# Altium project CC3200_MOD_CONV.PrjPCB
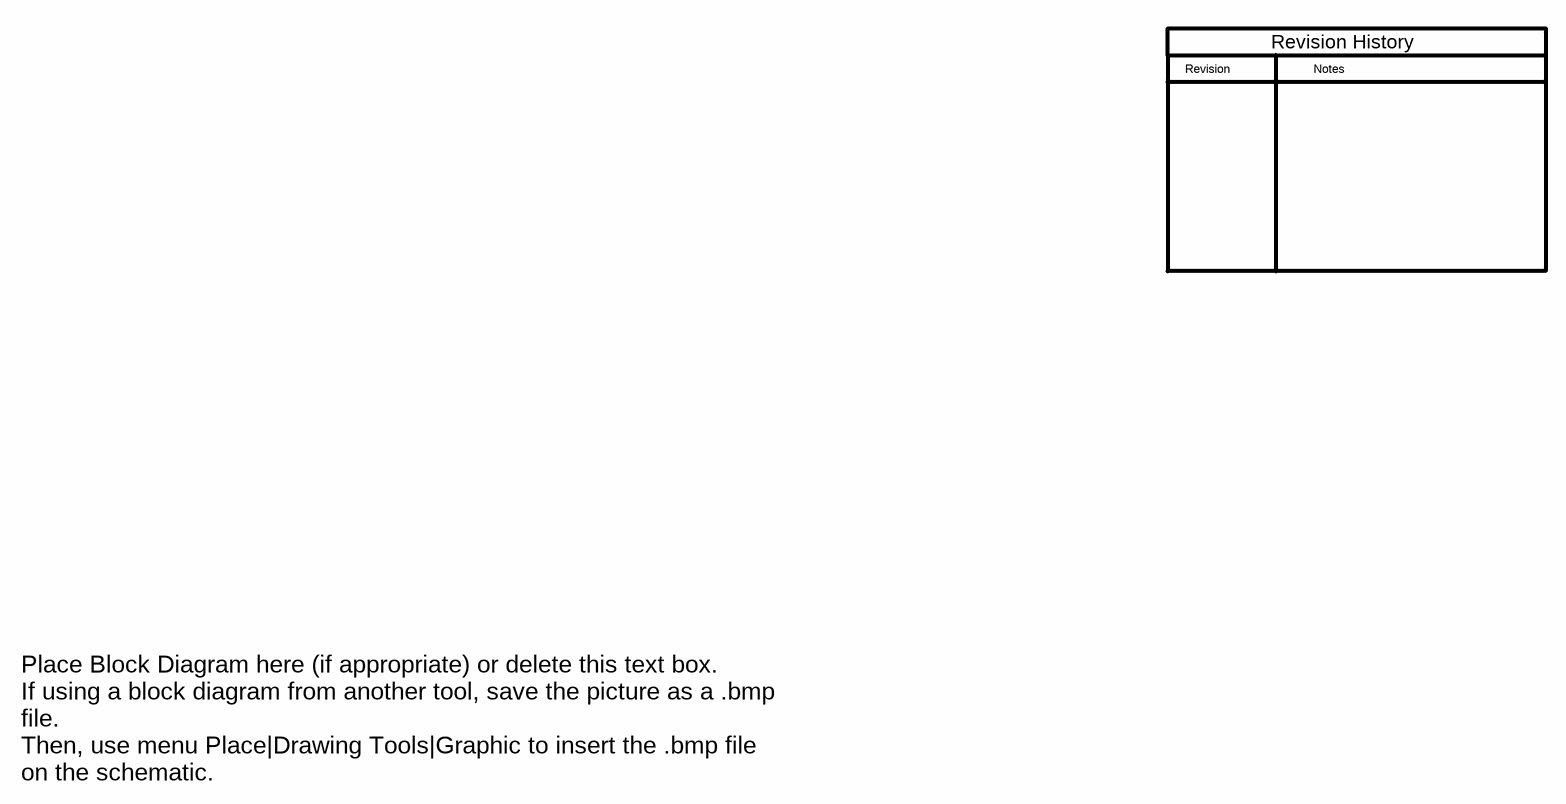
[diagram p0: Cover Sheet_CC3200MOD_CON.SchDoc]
TechSupport: http://www.ti.com/support; SCH_Rev: 1.0; PRJ_Title: Change in menu Project|Project Options|Parameters; PRJ_Number: TIDC-WIFI-METER-READING; PRJ_Engineer: Mars Leung; PRJ_Customer: Public Release; PCB_Rev: 1.0; PCB_Layout: Mars Leung; CopyrightYear: 2015
3 sheets, 82 parts. Net scope: flat (ports and power ports of the same name join across sheets).
Board file: CC3200MOD_CONV.PcbDoc
Sheets:
  Cover Sheet_CC3200MOD_CON.SchDoc
  CC3200MOD_CONV.SchDoc
  Hardware_CC3200MOD_CONV.SchDoc

## Sheet Cover Sheet_CC3200MOD_CON.SchDoc
size 431 x 279 mm; Date: Not shown in title block; ApprovedBy: Not shown in title block; CheckedBy: Not shown in title block; Author: Not shown in title block; CompanyName: Not shown in title block; Engineer: Not shown in title block; Organization: Not shown in title block; Address1: Not shown in title block; Address2: Not shown in title block; Address3: Not shown in title block; Address4: Not shown in title block; DocumentNumber: 1; Revision: Use project parameter SCH_Rev; SheetNumber: 1; SheetTotal: 1; PageSetup: Record=PageOptions|CenterHorizontal=True|CenterVertical=True|PrintScale=1.00|XCorrection=1.00|YCorrection=1.00|PrintKind=0|BorderSize=5000000|LeftOffset=0|BottomOffset=0|Orientation=2|PaperLength=1000|PaperWidth=1000|Scale=100|PaperSource=15|PrintQuality=600|MediaType=1|DitherType=10|PaperKind=Letter|PrintScaleMode=1

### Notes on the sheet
- Revision
- Notes
- Revision History
- Place Block Diagram here (if appropriate) or delete this text box.
  If using a block diagram from another tool, save the picture as a .bmp file.
  Then, use menu Place|Drawing Tools|Graphic to insert the .bmp file on the schematic.

## Sheet CC3200MOD_CONV.SchDoc: TIDC-WIFI-METER-READING
size 431 x 279 mm; Date: Not shown in title block; ApprovedBy: Not shown in title block; CheckedBy: Not shown in title block; Author: Not shown in title block; CompanyName: Not shown in title block; Engineer: Not shown in title block; Organization: Not shown in title block; Address1: Not shown in title block; Address2: Not shown in title block; Address3: Not shown in title block; Address4: Not shown in title block; DocumentNumber: 1; Revision: Use project parameter SCH_Rev; SheetNumber: 1; SheetTotal: 1; PageSetup: Record=PageOptions¦CenterHorizontal=True¦CenterVertical=True¦PrintScale=1.00¦XCorrection=1.00¦YCorrection=1.00¦PrintKind=0¦BorderSize=5000000¦LeftOffset=0¦BottomOffset=0¦Orientation=2¦PaperLength=1000¦PaperWidth=1000¦Scale=100¦PaperSource=15¦PrintQuality=600¦MediaType=1¦DitherType=10¦PaperKind=Letter¦PrintScaleMode=1
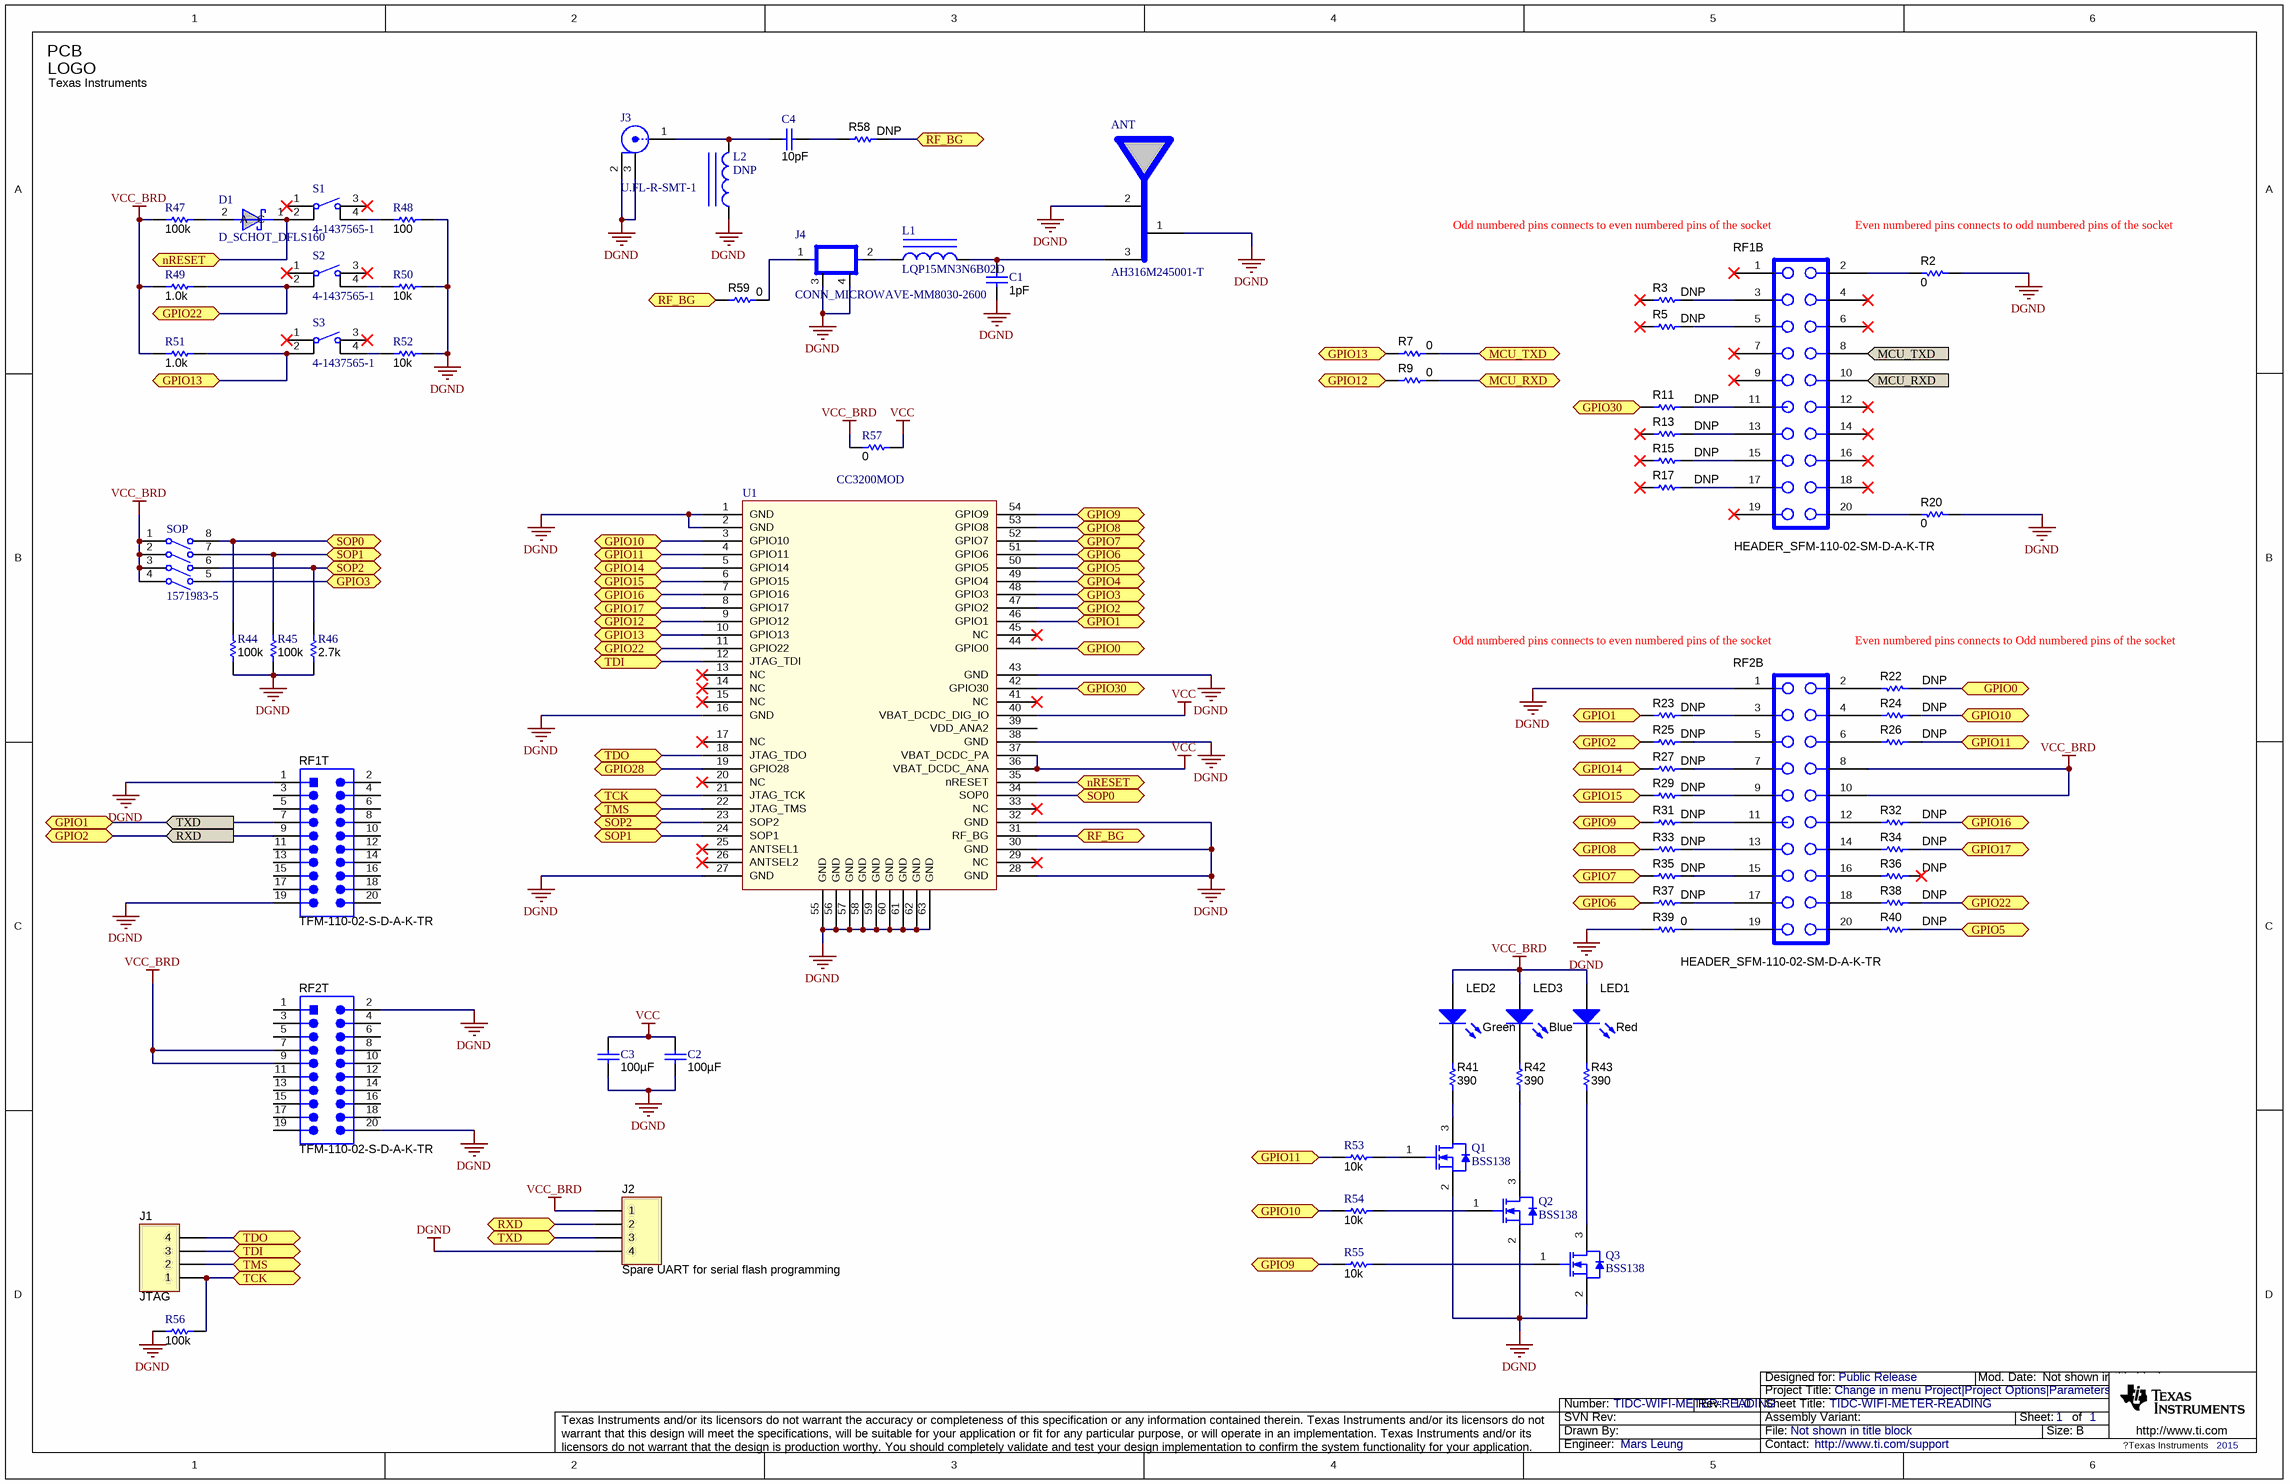
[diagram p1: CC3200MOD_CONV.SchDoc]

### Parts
ANT  AH316M245001-T  [AH316M]
C1  ValueDisplayed: 1pF  [0402]  (hidden comment: GRM1555C1H1R0BA01D)
C2  ValueDisplayed: 100µF  [1210]  (hidden comment: GRM32ER60J107ME20L)
C3  ValueDisplayed: 100µF  [1210]  (hidden comment: GRM32ER60J107ME20L)
C4  ValueDisplayed: 10pF  [0402]  (hidden comment: GRM1555C1H100JA01D)
D1  D_SCHOT_DFLS160  [POWERDI_123]
J1  JTAG  [HDR1X4]
J2  Spare UART for serial flash programming  [HDR1X4]
J3  U.FL-R-SMT-1  [CONN_UFL-R-SMT-1]
J4  CONN_MICROWAVE-MM8030-2600  [CONN_MICRO-MM8030-2600]
L1  LQP15MN3N6B02D  [LQP_0402]
L2  DNP  [LQP_0402]
LED1  Red  [0805-LED]
LED2  Green  [0805-LED]
LED3  Blue  [0805-LED]
Logo1  Texas Instruments  [TI_Stacked_SolderMask_Small]  (no BOM)
Q1  BSS138  [SOT-23]
Q2  BSS138  [SOT-23]
Q3  BSS138  [SOT-23]
R2  ValueDisplayed: 0  [0402]  (hidden comment: CRCW04020000Z0ED)
R3  ValueDisplayed: DNP  [0402]  (hidden comment: CRCW04020000Z0ED (Phantom))
R5  ValueDisplayed: DNP  [0402]  (hidden comment: CRCW04020000Z0ED (Phantom))
R7  ValueDisplayed: 0  [0402]  (hidden comment: CRCW04020000Z0ED)
R9  ValueDisplayed: 0  [0402]  (hidden comment: CRCW04020000Z0ED)
R11  ValueDisplayed: DNP  [0402]  (hidden comment: CRCW04020000Z0ED (Phantom))
R13  ValueDisplayed: DNP  [0402]  (hidden comment: CRCW04020000Z0ED (Phantom))
R15  ValueDisplayed: DNP  [0402]  (hidden comment: CRCW04020000Z0ED (Phantom))
R17  ValueDisplayed: DNP  [0402]  (hidden comment: CRCW04020000Z0ED (Phantom))
R20  ValueDisplayed: 0  [0402]  (hidden comment: CRCW04020000Z0ED)
R22  ValueDisplayed: DNP  [0402]  (hidden comment: CRCW04020000Z0ED (Phantom))
R23  ValueDisplayed: DNP  [0402]  (hidden comment: CRCW04020000Z0ED (Phantom))
R24  ValueDisplayed: DNP  [0402]  (hidden comment: CRCW04020000Z0ED (Phantom))
R25  ValueDisplayed: DNP  [0402]  (hidden comment: CRCW04020000Z0ED (Phantom))
R26  ValueDisplayed: DNP  [0402]  (hidden comment: CRCW04020000Z0ED (Phantom))
R27  ValueDisplayed: DNP  [0402]  (hidden comment: CRCW04020000Z0ED (Phantom))
R29  ValueDisplayed: DNP  [0402]  (hidden comment: CRCW04020000Z0ED (Phantom))
R31  ValueDisplayed: DNP  [0402]  (hidden comment: CRCW04020000Z0ED (Phantom))
R32  ValueDisplayed: DNP  [0402]  (hidden comment: CRCW04020000Z0ED (Phantom))
R33  ValueDisplayed: DNP  [0402]  (hidden comment: CRCW04020000Z0ED (Phantom))
R34  ValueDisplayed: DNP  [0402]  (hidden comment: CRCW04020000Z0ED (Phantom))
R35  ValueDisplayed: DNP  [0402]  (hidden comment: CRCW04020000Z0ED (Phantom))
R36  ValueDisplayed: DNP  [0402]  (hidden comment: CRCW04020000Z0ED (Phantom))
R37  ValueDisplayed: DNP  [0402]  (hidden comment: CRCW04020000Z0ED (Phantom))
R38  ValueDisplayed: DNP  [0402]  (hidden comment: CRCW04020000Z0ED (Phantom))
R39  ValueDisplayed: 0  [0402]  (hidden comment: CRCW04020000Z0ED)
R40  ValueDisplayed: DNP  [0402]  (hidden comment: CRCW04020000Z0ED (Phantom))
R41  ValueDisplayed: 390  [0402]  (hidden comment: CRCW0402390RJNED)
R42  ValueDisplayed: 390  [0402]  (hidden comment: CRCW0402390RJNED)
R43  ValueDisplayed: 390  [0402]  (hidden comment: CRCW0402390RJNED)
R44  ValueDisplayed: 100k  [0402]  (hidden comment: CRCW0402100KJNED)
R45  ValueDisplayed: 100k  [0402]  (hidden comment: CRCW0402100KJNED)
R46  ValueDisplayed: 2.7k  [0402]  (hidden comment: CRCW04022K70JNED)
R47  ValueDisplayed: 100k  [0402]  (hidden comment: CRCW0402100KJNED)
R48  ValueDisplayed: 100  [0402]  (hidden comment: CRCW0402100RJNED)
R49  ValueDisplayed: 1.0k  [0402]  (hidden comment: CRCW04021K00JNED)
R50  ValueDisplayed: 10k  [0402]  (hidden comment: CRCW040210K0JNED)
R51  ValueDisplayed: 1.0k  [0402]  (hidden comment: CRCW04021K00JNED)
R52  ValueDisplayed: 10k  [0402]  (hidden comment: CRCW040210K0JNED)
R53  ValueDisplayed: 10k  [0402]  (hidden comment: CRCW040210K0JNED)
R54  ValueDisplayed: 10k  [0402]  (hidden comment: CRCW040210K0JNED)
R55  ValueDisplayed: 10k  [0402]  (hidden comment: CRCW040210K0JNED)
R56  ValueDisplayed: 100k  [0402]  (hidden comment: CRCW0402100KJNED)
R57  ValueDisplayed: 0  [0805_HV]  (hidden comment: CRCW08050000Z0EA)
R58  ValueDisplayed: DNP  [0402]  (hidden comment: CRCW04020000Z0ED (Phantom))
R59  ValueDisplayed: 0  [0402]  (hidden comment: CRCW04020000Z0ED)
RF1B  HEADER_SFM-110-02-SM-D-A-K-TR  [HEADER_TFM-110-02-SM]
RF1T  TFM-110-02-S-D-A-K-TR  [Samtec_TFM-110-02-S-D-A-K]
RF2B  HEADER_SFM-110-02-SM-D-A-K-TR  [HEADER_TFM-110-02-SM]
RF2T  TFM-110-02-S-D-A-K-TR  [Samtec_TFM-110-02-S-D-A-K]
S1  4-1437565-1  [SW_FSM4JSMA]
S2  4-1437565-1  [SW_FSM4JSMA]
S3  4-1437565-1  [SW_FSM4JSMA]
SOP  1571983-5  [SW_1571983-5]
U1  CC3200MOD  [CC3200MOD]

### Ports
GPIO0, GPIO1, GPIO2, GPIO3, GPIO4, GPIO5, GPIO6, GPIO7, GPIO8, GPIO9, GPIO10, GPIO11, GPIO12, GPIO13, GPIO14, GPIO15, GPIO16, GPIO17, GPIO22, GPIO28, GPIO30, MCU_RXD, MCU_TXD, nRESET, RF_BG, RXD, SOP0, SOP1, SOP2, TCK, TDI, TDO, TMS, TXD

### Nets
DGND: ANT.1 ANT.2 C1.1 C2.2 C3.2 J2.4 J3.2 J3.3 J4.3 J4.4 L2.1 Q1.2(S) Q2.2(S) Q3.2(S) R2.1 R20.1 R39.1 R44.1 R45.1 R46.1 R48.2 R50.2 R52.2 R56.1 RF1T.1 RF1T.19 RF2B.1 RF2T.2 RF2T.20 U1.1(GND) U1.2(GND) U1.16(GND) U1.27(GND) U1.28(GND) U1.30(GND) U1.32(GND) U1.38(GND) U1.43(GND) U1.55(GND) U1.56(GND) U1.57(GND) U1.58(GND) U1.59(GND) U1.60(GND) U1.61(GND) U1.62(GND) U1.63(GND)
VCC: C2.1 C3.1 R57.2 U1.36(VBAT_DCDC_ANA) U1.37(VBAT_DCDC_PA) U1.40(VBAT_DCDC_DIG_IO)
VCC_BRD: J2.1 LED1.1(A) LED2.1(A) LED3.1(A) R47.1 R49.1 R51.1 R57.1 RF2B.8 RF2B.10 RF2T.7 RF2T.9 SOP.1(A1) SOP.2(A2) SOP.3(A3) SOP.4(A4)
GPIO0: R22.1 U1.44(GPIO0) ; port GPIO0
GPIO1: J2.3 R23.1 RF1T.7 U1.46(GPIO1) ; port TXD, port GPIO1
GPIO2: J2.2 R25.1 RF1T.9 U1.47(GPIO2) ; port RXD, port GPIO2
GPIO3: SOP.5(B4) U1.48(GPIO3) ; port GPIO3
GPIO4: U1.49(GPIO4) ; port GPIO4
GPIO5: R40.2 U1.50(GPIO5) ; port GPIO5
GPIO6: R37.1 U1.51(GPIO6) ; port GPIO6
GPIO7: R35.1 U1.52(GPIO7) ; port GPIO7
GPIO8: R33.1 U1.53(GPIO8) ; port GPIO8
GPIO9: R31.1 R55.1 U1.54(GPIO9) ; port GPIO9
GPIO10: R24.2 R54.1 U1.3(GPIO10) ; port GPIO10
GPIO11: R26.2 R53.1 U1.4(GPIO11) ; port GPIO11
GPIO12: R9.1 U1.9(GPIO12) ; port GPIO12
GPIO13: R7.1 R51.2 S3.2 U1.10(GPIO13) ; port GPIO13
GPIO14: R27.1 U1.5(GPIO14) ; port GPIO14
GPIO15: R29.1 U1.6(GPIO15) ; port GPIO15
GPIO16: R32.2 U1.7(GPIO16) ; port GPIO16
GPIO17: R34.2 U1.8(GPIO17) ; port GPIO17
GPIO22: R38.2 R49.2 S2.2 U1.11(GPIO22) ; port GPIO22
GPIO28: U1.19(GPIO28) ; port GPIO28
GPIO30: R11.1 U1.42(GPIO30) ; port GPIO30
MCU_RXD: R9.2 RF1B.10 ; port MCU_RXD
MCU_TXD: R7.2 RF1B.8 ; port MCU_TXD
nRESET: D1.1(C) S1.2 U1.35(nRESET) ; port nRESET
RF_BG: R58.2 R59.1 U1.31(RF_BG) ; port RF_BG
SOP0: R44.2 SOP.8(B1) U1.34(SOP0) ; port SOP0
SOP1: R45.2 SOP.7(B2) U1.24(SOP1) ; port SOP1
SOP2: R46.2 SOP.6(B3) U1.23(SOP2) ; port SOP2
TCK: J1.1 R56.2 U1.21(JTAG_TCK) ; port TCK
TDI: J1.3 U1.12(JTAG_TDI) ; port TDI
TDO: J1.4 U1.18(JTAG_TDO) ; port TDO
TMS: J1.2 U1.22(JTAG_TMS) ; port TMS
NetANT_3: ANT.3 C1.2 L1.2
NetC4_1: C4.1 R58.1
NetC4_2: C4.2 J3.1 L2.2
NetD1_2: D1.2(A) R47.2
NetJ4_1: J4.1 R59.2
NetJ4_2: J4.2 L1.1
NetLED1_2: LED1.2(K) R43.2
NetLED2_2: LED2.2(K) R41.2
NetLED3_2: LED3.2(K) R42.2
NetQ1_1: Q1.1(G) R53.2
NetQ1_3: Q1.3(D) R41.1
NetQ2_1: Q2.1(G) R54.2
NetQ2_3: Q2.3(D) R42.1
NetQ3_1: Q3.1(G) R55.2
NetQ3_3: Q3.3(D) R43.1
NetR2_2: R2.2 RF1B.2
NetR3_2: R3.2 RF1B.3
NetR5_2: R5.2 RF1B.5
NetR11_2: R11.2 RF1B.11
NetR13_2: R13.2 RF1B.13
NetR15_2: R15.2 RF1B.15
NetR17_2: R17.2 RF1B.17
NetR20_2: R20.2 RF1B.20
NetR22_2: R22.2 RF2B.2
NetR23_2: R23.2 RF2B.3
NetR24_1: R24.1 RF2B.4
NetR25_2: R25.2 RF2B.5
NetR26_1: R26.1 RF2B.6
NetR27_2: R27.2 RF2B.7
NetR29_2: R29.2 RF2B.9
NetR31_2: R31.2 RF2B.11
NetR32_1: R32.1 RF2B.12
NetR33_2: R33.2 RF2B.13
NetR34_1: R34.1 RF2B.14
NetR35_2: R35.2 RF2B.15
NetR36_1: R36.1 RF2B.16
NetR37_2: R37.2 RF2B.17
NetR38_1: R38.1 RF2B.18
NetR39_2: R39.2 RF2B.19
NetR40_1: R40.1 RF2B.20
NetR48_1: R48.1 S1.4
NetR50_1: R50.1 S2.4
NetR52_1: R52.1 S3.4

Not connected (* = marked no-connect by the designer): R3 1*; R5 1*; R13 1*; R15 1*; R17 1*; R36 2*; RF1B 1* 4* 6* 7* 9* 12* 14* 16* 18* 19*; RF1T 2 3 4 5 6 8 10 11 12 13 14 15 16 17 18 20; RF2T 1 3 4 5 6 8 10 11 12 13 14 15 16 17 18 19; S1 1* 3*; S2 1* 3*; S3 1* 3*; U1 13(NC)* 14(NC)* 15(NC)* 17(NC)* 20(NC)* 25(ANTSEL1)* 26(ANTSEL2)* 29(NC)* 33(NC)* 39(VDD_ANA2) 41(NC)* 45(NC)*

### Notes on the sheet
- (near RF1B) Odd numbered pins connects to even numbered pins of the socket
- Even numbered pins connects to odd numbered pins of the socket
- (near RF2B) Odd numbered pins connects to even numbered pins of the socket
- Even numbered pins connects to Odd numbered pins of the socket

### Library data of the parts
ANT = AH316M245001-T: Manufacturer: Taiyo Yuden; Value: 2.45-GHz Ant
C1 = GRM1555C1H1R0BA01D: CAP, CERM, 1 pF, 50 V, +/- 10%, C0G/NP0, 0402; Manufacturer: MuRata; Polarized: N; CompType: Capacitor; Value: 1pF; U/M: EA; Cap_F: 0.000000000001; Tolerance_%: 10; Value1: Unknown; VDC_V: 50; Value2: 50V; TaMin_C: -55; TaMax_C: 125
C2 C3 = GRM32ER60J107ME20L: CAP, CERM, 100 µF, 6.3 V, +/- 20%, X5R, 1210; Manufacturer: MuRata; Polarized: N; CompType: Capacitor; Value: 100uF; U/M: EA; Cap_F: 0.0001; Tolerance_%: 20; ESR_ohm: 0.002; Value1: 0.002 ohm; VDC_V: 6.3; Value2: 6.3V; TaMin_C: -55; TaMax_C: 85
C4 = GRM1555C1H100JA01D: CAP, CERM, 10 pF, 50 V, +/- 5%, C0G/NP0, 0402; Manufacturer: MuRata; Polarized: N; CompType: Capacitor; Value: 10pF; U/M: EA; Cap_F: 0.00000000001; Tolerance_%: 5; Value1: Unknown; VDC_V: 50; Value2: 50V; TaMin_C: -55; TaMax_C: 125
D1 = D_SCHOT_DFLS160: Diode, Schottky, 1A, 60V; Manufacturer: Diodes; Area: 53200
J1 J2 = Header 4: Header, 4-Pin
J3 = U.FL-R-SMT-1: Connector, Ultra-Mini Coaxial, SMD; Manufacturer: Hirose Electric Co. Ltd.; SymbolCreator: a0412235; U/M: EA
J4 = CONN_MICROWAVE-MM8030-2600: Connector, Micrwave, 50 Ohm Coax; Manufacturer: murata; Area: 9 mm
L1 = LQP15MN10NG02D: Inductor, Film,  3.6 nH, 0.1 A, 1.3 ohm, SMD; Manufacturer: MuRata; Value: 3.6nH; Ind_H: 3.6E-9; Imax_A: 0.1; Irms: 0.1A @ C rise; DCR_ohm: 0.5; Value1: 0.5 ohm; Value2: 0.1A
L2 = LQP15MN10NG02D: Inductor, Film,  3.6 nH, 0.1 A, 1.3 ohm, SMD; PartNumber: LQP15MN3N6B02D; Manufacturer: MuRata; Ind_H: 3.6E-9; ValueDisplayed: 3.6nH; Imax_A: 0.1; Irms: 0.1A @ C rise; DCR_ohm: 0.5; Value1: 0.5 ohm; Value2: 0.1A
LED1-LED3 = LED-0805: Manufacturer: Used in BOM report; SymbolVersion: use current date i.e. 2008-05-20; SymbolCreator: Use LDAP id; CompType: Used in some BOM reports.  Useful for finding later.; U/M: EA, IN, or GM
Logo1 = TI_Logo: Texas Instrument Corporate Signature; SymbolCreator: codlsc
Q1-Q3 = BSS138: MOSFET, N-CH, 50 V, 0.22 A, SOT-23; Manufacturer: Fairchild Semiconductor; Alternate Manufacturer: None; U/M: EA; ChType: N; Value: 50V; VdsMax_V: 50; Value1: 6 ohm; Rdson45_ohm: 6; Value2: 1.7 nC; QgTyp_nC: 1.7; Vgs_V: 20; IdsMax_A: 0.22
R2 R7 R9 R20 R39 R59 = CRCW04020000Z0ED: RES, 0, 5%, 0.063 W, 0402; Manufacturer: Vishay-Dale; CompType: Resistor; Value: 0; Value_Code: 0000; Tolerance_%: 5; Power_W: 0.063; Value2: 0.063W; VDC_V: 50; TempCo: 200 ppm/C; EIA_Code: E24; U/M: EA
R3 R5 R11 R13 R15 R17 R22-R27 R29 R31-R38 R40 R58 = CRCW04020000Z0ED: RES, DNP, 5%, 0.063 W, 0402; Manufacturer: Vishay-Dale; CompType: Resistor; Value_Code: 0000; Tolerance_%: 5; Power_W: 0.063; Value2: 0.063W; VDC_V: 50; TempCo: 200 ppm/C; EIA_Code: E24; U/M: EA
R41-R43 = CRCW0402390RJNED: RES, 390, 5%, 0.063 W, 0402; Manufacturer: Vishay-Dale; CompType: Resistor; Value: 390; Value_Code: 390R; Tolerance_%: 5; Power_W: 0.063; Value2: 0.063W; VDC_V: 50; TempCo: 200 ppm/C; EIA_Code: E24; U/M: EA
R44 R45 R47 R56 = CRCW0402100KJNED: RES, 100 k, 5%, 0.063 W, 0402; Manufacturer: Vishay-Dale; CompType: Resistor; Value: 100k; Res_ohm: 100000; Tolerance_%: 5; Power_W: 0.063; Value2: 0.063W; VDC_V: 50; TempCo: 200 ppm/C; EIA_Code: E24; U/M: EA
R46 = CRCW04022K70JNED: RES, 2.7 k, 5%, 0.063 W, 0402; Manufacturer: Vishay-Dale; CompType: Resistor; Value: 2.7k; Res_ohm: 2700; Value_Code: 2k70; Tolerance_%: 5; Power_W: 0.063; Value2: 0.063W; VDC_V: 50; TempCo: 200 ppm/C; EIA_Code: E24; U/M: EA
R48 = CRCW0402100RJNED: RES, 100, 5%, 0.063 W, 0402; Manufacturer: Vishay-Dale; CompType: Resistor; Value: 100; Value_Code: 100R; Tolerance_%: 5; Power_W: 0.063; Value2: 0.063W; VDC_V: 50; TempCo: 200 ppm/C; EIA_Code: E24; U/M: EA
R49 R51 = CRCW04021K00JNED: RES, 1.0 k, 5%, 0.063 W, 0402; Manufacturer: Vishay-Dale; CompType: Resistor; Value: 1.0k; Res_ohm: 1000; Value_Code: 1k00; Tolerance_%: 5; Power_W: 0.063; Value2: 0.063W; VDC_V: 50; TempCo: 200 ppm/C; EIA_Code: E24; U/M: EA
R50 R52-R55 = CRCW040210K0JNED: RES, 10 k, 5%, 0.063 W, 0402; Manufacturer: Vishay-Dale; CompType: Resistor; Value: 10k; Res_ohm: 10000; Value_Code: 10k0; Tolerance_%: 5; Power_W: 0.063; Value2: 0.063W; VDC_V: 50; TempCo: 200 ppm/C; EIA_Code: E24; U/M: EA
R57 = CRCW08050000Z0EA: RES, 0, 5%, 0.125 W, 0805; Manufacturer: Vishay-Dale; CompType: Resistor; Value: 0; Value_Code: 0000; Tolerance_%: 5; Power_W: 0.125; Value2: 0.125W; VDC_V: 150; TempCo: 200 ppm/C; EIA_Code: E24; U/M: EA
RF1B RF2B = HEADER_TFM-110-02-SM-D-A-K-TR: Header, SMT 10X2 pin, Shrouded; Manufacturer: Samtec; area: 119800
RF1T RF2T = TFM-110-02-S-D-A-K-TR: CONN SHRD HDR HDR 20 POS 1.27MM SLDR ST SMD; Manufacturer: Samtec; SymbolCreator: a0412235; CompType: Header; U/M: EA
S1-S3 = 4-1437565-1: Switch, Tactile, SPST-NO, 0.05A, 12V, SMT; Manufacturer: TE Connectivity; SymbolCreator: a0412235; VDC_V: 12; SwitchFunction: Off-Mom; PositionCount: 1; CurrentRating_mA: 50
SOP = 1571983-5: Switch, SPST, 4 Pos, Top Actuated, SMD; Manufacturer: TE Connectivity; SymbolCreator: a0412235; VDC_V: 24; PositionCount: 4; CurrentRating_mA: 25

## Sheet Hardware_CC3200MOD_CONV.SchDoc: TIDC-WIFI-METER-READING
size 431 x 279 mm; Date: Not shown in title block; ApprovedBy: Not shown in title block; CheckedBy: Not shown in title block; Author: Not shown in title block; CompanyName: Not shown in title block; Engineer: Not shown in title block; Organization: Not shown in title block; Address1: Not shown in title block; Address2: Not shown in title block; Address3: Not shown in title block; Address4: Not shown in title block; DocumentNumber: 1; Revision: Use project parameter SCH_Rev; SheetNumber: 1; SheetTotal: 1; PageSetup: Record=PageOptions¦CenterHorizontal=True¦CenterVertical=True¦PrintScale=1.00¦XCorrection=1.00¦YCorrection=1.00¦PrintKind=0¦BorderSize=5000000¦LeftOffset=0¦BottomOffset=0¦Orientation=2¦PaperLength=1000¦PaperWidth=1000¦Scale=100¦PaperSource=15¦PrintQuality=600¦MediaType=1¦DitherType=10¦PaperKind=Letter¦PrintScaleMode=1
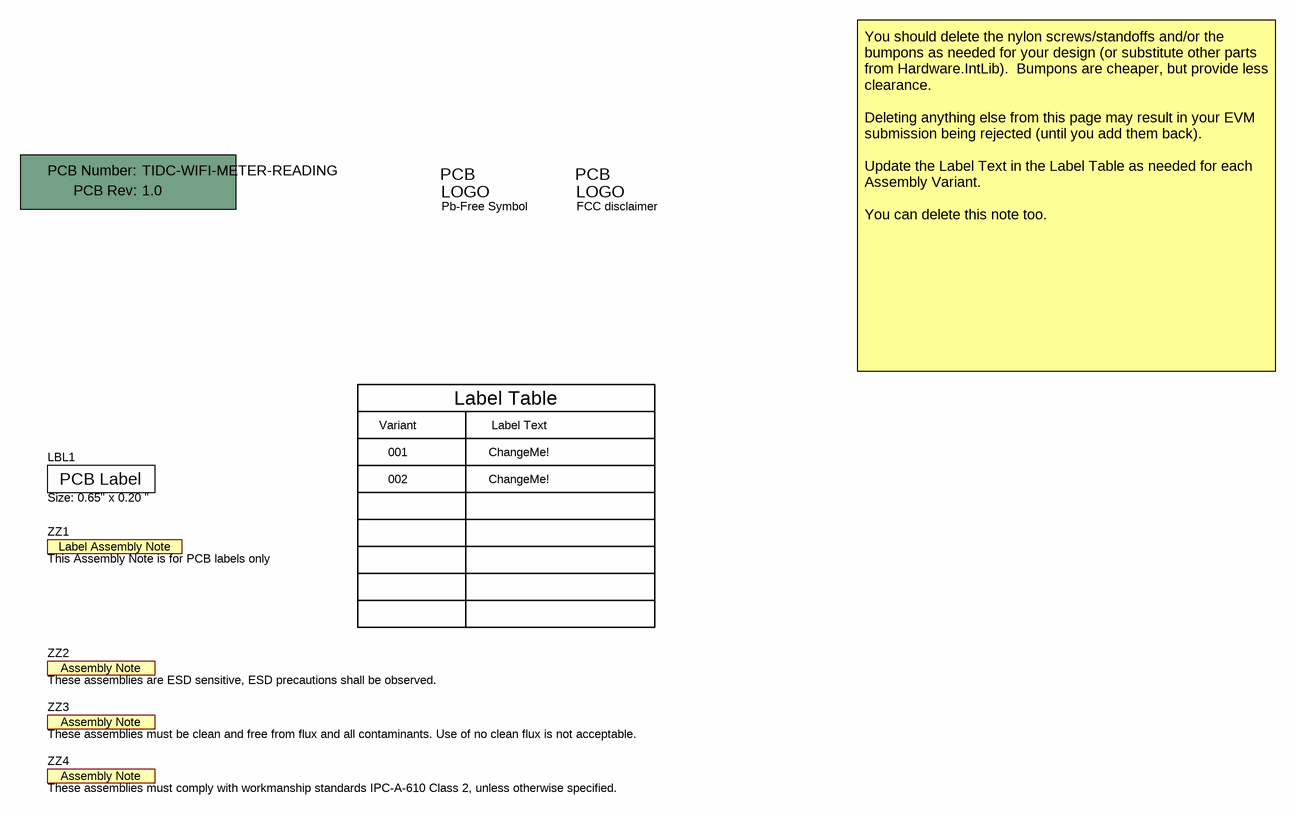
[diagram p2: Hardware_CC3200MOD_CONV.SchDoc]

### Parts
!PCB  Printed Circuit Board  (value not drawn)  (mechanical)
LBL1  Size: 0.65" x 0.20 "  [Label_650x200]
Logo2  Pb-Free Symbol  [Pb-Free_Overlay_Small]  (no BOM)
Logo3  FCC disclaimer  [FCC_disclaimer_stacked]  (no BOM)
ZZ1  This Assembly Note is for PCB labels only  [AssemblyNoteLabel]  (no BOM)
ZZ2  These assemblies are ESD sensitive, ESD precautions shall be observed.  [AssemblyNote]  (no BOM)
ZZ3  These assemblies must be clean and free from flux and all contaminants. Use of no clean flux is not acceptable.  [AssemblyNote]  (no BOM)
ZZ4  These assemblies must comply with workmanship standards IPC-A-610 Class 2, unless otherwise specified.  [AssemblyNote]  (no BOM)

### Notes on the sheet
- Variant
- Label Table
- Label Text
- You should delete the nylon screws/standoffs and/or the bumpons as needed for your design (or substitute other parts from Hardware.IntLib).  Bumpons are cheaper, but provide less clearance.
  Deleting anything else from this page may result in your EVM submission being rejected (until you add them back).
  Update the Label Text in the Label Table as needed for each Assembly Variant.
  You can delete this note too.
- 001
- 002
- ChangeMe!

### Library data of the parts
!PCB = PCB: Manufacturer: Any; PartNumber: TIDC-WIFI-METER-READING; SymbolCreator: a0412235
LBL1 = THT-14-423-10: Thermal Transfer Printable Labels, 0.650" W x 0.200" H - 10,000 per roll; Manufacturer: Brady; SymbolCreator: a0412235; CompType: Label
Logo2 = Pb-Free: SymbolCreator: a0412235
Logo3 = FCC_disclaimer: SymbolCreator: codlsc
ZZ1 = AssemblyNoteLabel: SymbolCreator: a0412235
ZZ2-ZZ4 = AssemblyNote: SymbolCreator: codlsc

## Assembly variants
001: not fitted FID1 FID2 FID3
